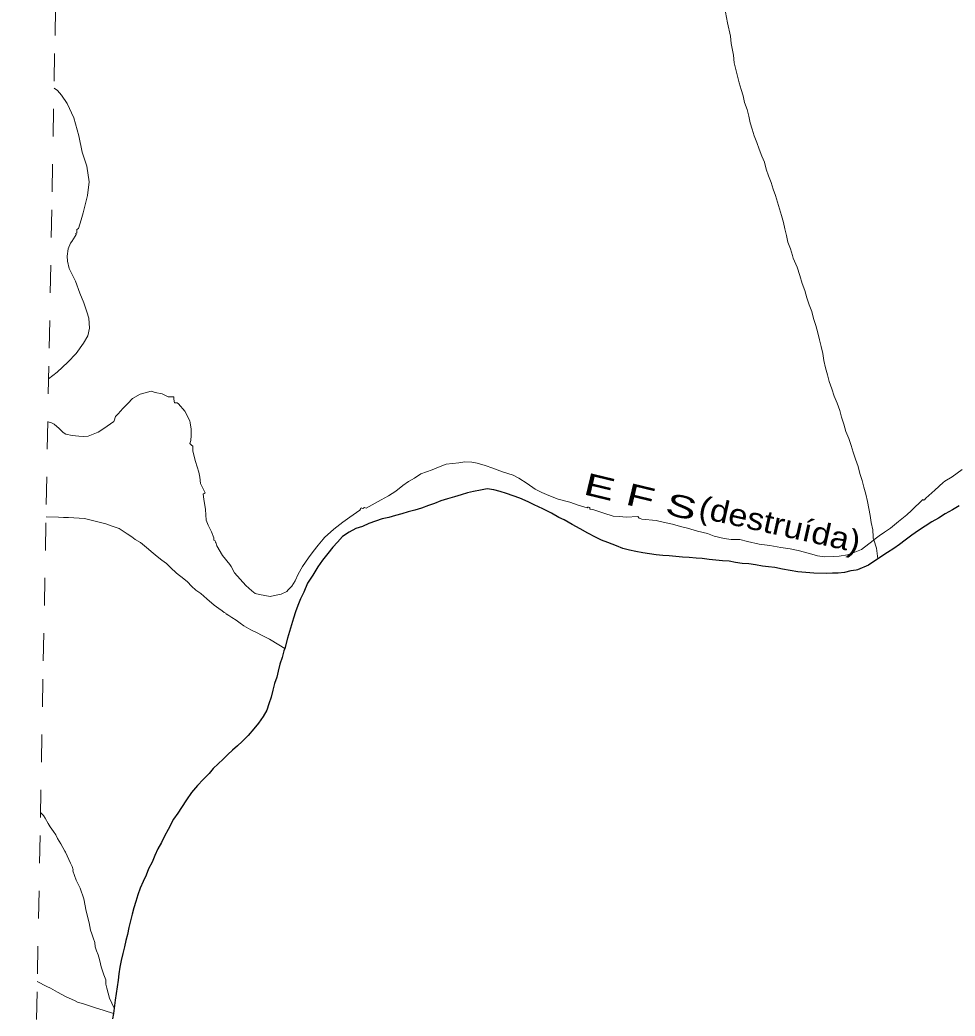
# Model space of a CAD drawing. Extents: x 781.9 to 808.1, y 7453.3 to 7481.5.
# Drawn here: x 782.028 to 785.41, y 7463.258 to 7466.859 of the extents above; entities that cross this region are included whole.
import ezdxf
from ezdxf.enums import TextEntityAlignment as Align

# ---------------------------------------------------------------- set-up
doc = ezdxf.new("R2010")
doc.units = 0
doc.header["$LTSCALE"] = 0.032
for name, pattern in [('DOTTED', [1.5, 0.3, -1.2]), ('LONG_DASHED', [7.5, 6, -1.5]), ('MEDIUM_DASHED', [4.5, 3, -1.5]), ('SHORT_DASHED', [2.7, 1.5, -1.2])]:
    doc.linetypes.add(name, pattern=pattern)
for name, color, linetype, lineweight in [('19', 7, 'DOTTED', 13), ('35', 7, 'SHORT_DASHED', 13), ('4', 7, 'LONG_DASHED', 25), ('5', 7, 'LONG_DASHED', 13), ('6', 7, 'MEDIUM_DASHED', 13)]:
    doc.layers.add(name, color=color, linetype=linetype, lineweight=lineweight)
doc.layers.add('61', color=7, linetype='Continuous')

msp = doc.modelspace()

# ---------------------------------------------------------------- linework, layer by layer
at = {"layer": '19'}
for points in [[(782.1515, 7466.6129), (782.1639, 7466.6037), (782.1791, 7466.5869), (782.1988, 7466.5576), (782.2233, 7466.5051), (782.2406, 7466.4397), (782.2538, 7466.3815), (782.2703, 7466.3306), (782.2791, 7466.2744), (782.2731, 7466.2243), (782.2591, 7466.1718), (782.2567, 7466.1613), (782.2502, 7466.137), (782.2397, 7466.1053), (782.234, 7466.1013), (782.234, 7466.094), (782.234, 7466.0891), (782.2307, 7466.0875), (782.2315, 7466.0834), (782.2275, 7466.0778), (782.2157, 7466.0583), (782.2105, 7466.0518), (782.2024, 7466.0316), (782.1996, 7466.0055), (782.2004, 7465.9871), (782.2068, 7465.9606), (782.2289, 7465.9145), (782.2449, 7465.872), (782.2597, 7465.8363), (782.2702, 7465.8034), (782.2778, 7465.7805), (782.2802, 7465.7444), (782.2734, 7465.7175), (782.2581, 7465.6903), (782.232, 7465.6538), (782.2015, 7465.6217), (782.1634, 7465.586), (782.1318, 7465.5621)], [(782.4351, 7465.4908), (782.4183, 7465.4732), (782.4007, 7465.4548), (782.3831, 7465.4356), (782.3743, 7465.4259), (782.3685, 7465.4105), (782.3678, 7465.4081)], [(783.9157, 7465.1505), (783.8917, 7465.1633), (783.8621, 7465.1841), (783.8325, 7465.2025), (783.8117, 7465.2137), (783.7733, 7465.2257), (783.7389, 7465.2385), (783.7109, 7465.2481), (783.6813, 7465.2569), (783.6621, 7465.2609), (783.6373, 7465.2617), (783.6149, 7465.2585), (783.5693, 7465.2529), (783.5357, 7465.2401), (783.519, 7465.233), (783.4777, 7465.2183), (783.4553, 7465.2032), (783.4329, 7465.1912), (783.4129, 7465.176), (783.3881, 7465.156), (783.3617, 7465.1384), (783.3345, 7465.1248), (783.2807, 7465.0943), (783.2742, 7465.0968), (783.2685, 7465.0935), (783.2628, 7465.0951), (783.2612, 7465.0927), (783.258, 7465.087), (783.2215, 7465.0619), (783.1964, 7465.0441), (783.1631, 7465.0181), (783.1298, 7464.9889), (783.125, 7464.9824), (783.1066, 7464.9608), (783.089, 7464.9376), (783.0722, 7464.9152), (783.0498, 7464.8832), (783.0346, 7464.8552), (783.0234, 7464.832), (783.0114, 7464.8128), (782.9986, 7464.7992), (782.9936, 7464.7935), (782.9734, 7464.7838), (782.9491, 7464.7789), (782.9337, 7464.7749), (782.894, 7464.7822), (782.8785, 7464.7862), (782.8664, 7464.7951), (782.8453, 7464.8146), (782.8039, 7464.8608), (782.7918, 7464.8835), (782.7869, 7464.8908), (782.7609, 7464.9233), (782.7399, 7464.9581), (782.7366, 7464.9702), (782.735, 7464.9711), (782.7342, 7464.9768), (782.7294, 7464.9792), (782.7294, 7464.9873), (782.7204, 7465.0084), (782.7091, 7465.0327), (782.7018, 7465.0514), (782.6994, 7465.0895), (782.6937, 7465.1268), (782.6913, 7465.1454), (782.6977, 7465.1494), (782.6815, 7465.1835), (782.6783, 7465.2062), (782.675, 7465.2249), (782.6637, 7465.263), (782.654, 7465.3003), (782.6532, 7465.3116), (782.6539, 7465.3181), (782.6483, 7465.3221), (782.6426, 7465.3278), (782.6467, 7465.3391), (782.6475, 7465.357), (782.6475, 7465.3797), (782.6434, 7465.4024), (782.6426, 7465.4097), (782.6248, 7465.4446), (782.6021, 7465.4713), (782.5972, 7465.4746), (782.5875, 7465.4754), (782.5842, 7465.4884), (782.5842, 7465.4916), (782.585, 7465.4972), (782.5648, 7465.4973), (782.5591, 7465.4997), (782.5421, 7465.507), (782.5178, 7465.5119), (782.5023, 7465.5167), (782.4626, 7465.5062), (782.4358, 7465.4908), (782.4351, 7465.4908)], [(782.3678, 7465.4081), (782.3321, 7465.3822), (782.3113, 7465.3686), (782.2929, 7465.3614), (782.2753, 7465.355), (782.2577, 7465.3534), (782.2409, 7465.3542), (782.2169, 7465.3566), (782.1945, 7465.3614), (782.1841, 7465.3678), (782.1697, 7465.3822), (782.1522, 7465.3982), (782.1418, 7465.403), (782.1289, 7465.4058)], [(785.4357, 7465.2338), (785.3992, 7465.207), (785.3733, 7465.1916), (785.3676, 7465.1876), (785.3368, 7465.16), (785.3043, 7465.13), (785.2995, 7465.1243), (785.2954, 7465.1227), (785.2938, 7465.1251), (785.2524, 7465.0854), (785.2362, 7465.0708), (785.2054, 7465.0465), (785.1762, 7465.0222), (785.1554, 7465.007), (785.1354, 7464.9942), (785.1162, 7464.9793)], [(784.0792, 7465.0959), (784.0679, 7465.0992), (784.0469, 7465.1049), (784.0165, 7465.1161), (783.9749, 7465.1273), (783.9405, 7465.1401), (783.9157, 7465.1505)], [(785.1162, 7464.9793), (785.1138, 7464.9774), (785.0722, 7464.9446), (785.0482, 7464.935), (785.021, 7464.9254), (784.9906, 7464.9214), (784.9706, 7464.9198), (784.9386, 7464.919), (784.9122, 7464.9222), (784.8842, 7464.9302), (784.8426, 7464.9414), (784.8138, 7464.9478), (784.7802, 7464.9526), (784.7402, 7464.9598), (784.7018, 7464.9638), (784.6594, 7464.9742), (784.6314, 7464.9806), (784.6002, 7464.9814), (784.5754, 7464.9846), (784.5394, 7464.9934), (784.5146, 7465.0022), (784.4782, 7465.0116), (784.443, 7465.022), (784.4166, 7465.0276), (784.3877, 7465.0364), (784.3542, 7465.0436), (784.3286, 7465.05), (784.2771, 7465.0546), (784.2714, 7465.057), (784.2682, 7465.0578), (784.2625, 7465.0643), (784.2204, 7465.0619), (784.196, 7465.0643), (784.1741, 7465.0652), (784.1393, 7465.0765), (784.1036, 7465.0878), (784.0922, 7465.0903), (784.089, 7465.0911), (784.0898, 7465.0968), (784.0841, 7465.0984), (784.0817, 7465.0984), (784.0792, 7465.0959)]]:
    msp.add_lwpolyline(points, dxfattribs=at)
at = {"layer": '35'}
msp.add_lwpolyline([(782.0281, 7460.0199), (782.0387, 7460.5852), (782.0493, 7461.1504), (782.0599, 7461.7157), (782.0704, 7462.2809), (782.081, 7462.8462), (782.0916, 7463.4115), (782.1022, 7463.9767), (782.1127, 7464.542), (782.1233, 7465.1072), (782.1339, 7465.6725), (782.1444, 7466.2377), (782.155, 7466.803), (782.1655, 7467.3682)], dxfattribs=at)
at = {"layer": '4'}
for points in [[(784.5447, 7464.9062), (784.5203, 7464.9087), (784.496, 7464.9119), (784.4733, 7464.9135), (784.449, 7464.916), (784.4247, 7464.9176), (784.4004, 7464.92), (784.376, 7464.9216), (784.3533, 7464.9232), (784.329, 7464.9257), (784.3047, 7464.9289), (784.2804, 7464.933), (784.256, 7464.9378), (784.2333, 7464.9427), (784.209, 7464.9484), (784.1855, 7464.9581), (784.1539, 7464.9703), (784.1312, 7464.9792), (784.1093, 7464.9897), (784.0817, 7465.0043), (784.0541, 7465.0197), (784.0257, 7465.0351), (783.9966, 7465.0522), (783.9771, 7465.0603), (783.9503, 7465.0765), (783.9196, 7465.0919), (783.888, 7465.1065), (783.8668, 7465.117), (783.8361, 7465.13), (783.8117, 7465.1389), (783.7874, 7465.1478), (783.7647, 7465.1551), (783.742, 7465.1608), (783.7177, 7465.1641), (783.6934, 7465.1592), (783.669, 7465.1551), (783.6463, 7465.1495), (783.6236, 7465.143), (783.5993, 7465.1357), (783.575, 7465.1276), (783.5507, 7465.1203), (783.528, 7465.1113), (783.5053, 7465.104), (783.4809, 7465.0943), (783.4566, 7465.087), (783.4323, 7465.0805), (783.4096, 7465.0741), (783.3869, 7465.0676), (783.3626, 7465.0611), (783.3383, 7465.0554), (783.3139, 7465.0473), (783.2896, 7465.0384), (783.2669, 7465.0286), (783.2426, 7465.0206), (783.2183, 7465.0075), (783.1947, 7464.9922), (783.1761, 7464.9719), (783.1599, 7464.9532), (783.1412, 7464.9306), (783.1226, 7464.9062), (783.1055, 7464.8827), (783.0869, 7464.8527), (783.0683, 7464.8235), (783.0545, 7464.7911), (783.0423, 7464.7668), (783.0334, 7464.7425), (783.0245, 7464.7198), (783.018, 7464.6971), (783.0107, 7464.6727), (783.0026, 7464.6484), (782.9953, 7464.6241), (782.986, 7464.5874)], [(785.4252, 7465.1024), (785.4008, 7465.0886), (785.3749, 7465.074), (785.3497, 7465.0586), (785.3261, 7465.0449), (785.3019, 7465.0294), (785.2776, 7465.0141), (785.2541, 7464.9962), (785.2298, 7464.9784), (785.2087, 7464.963), (785.1884, 7464.9484), (785.1657, 7464.9338), (785.1305, 7464.9114)], [(785.1305, 7464.9114), (785.0969, 7464.8882), (785.0577, 7464.8713), (785.053, 7464.8697), (785.0327, 7464.8673), (785.01, 7464.8616), (784.9873, 7464.86), (784.9663, 7464.86), (784.9452, 7464.8584), (784.8996, 7464.8592), (784.842, 7464.8648), (784.786, 7464.8736), (784.7587, 7464.8795), (784.736, 7464.8827), (784.7133, 7464.8852), (784.689, 7464.8892)], [(784.689, 7464.8892), (784.6647, 7464.8933), (784.6403, 7464.8949), (784.616, 7464.8981), (784.5933, 7464.9022), (784.569, 7464.9038), (784.5447, 7464.9062)], [(782.986, 7464.5874), (782.9831, 7464.5787), (782.9766, 7464.5544), (782.9677, 7464.53), (782.9621, 7464.5057), (782.9572, 7464.483), (782.9483, 7464.4603), (782.9434, 7464.436), (782.9369, 7464.4117), (782.9288, 7464.3874), (782.9207, 7464.3647), (782.9077, 7464.3419), (782.8915, 7464.3176), (782.8745, 7464.2973), (782.8542, 7464.273), (782.8315, 7464.2511), (782.8145, 7464.2348), (782.7974, 7464.2195), (782.7796, 7464.2041), (782.7626, 7464.1871), (782.7448, 7464.1708), (782.7269, 7464.153), (782.7123, 7464.1352), (782.6912, 7464.1141)], [(782.6912, 7464.1141), (782.6701, 7464.0914), (782.6491, 7464.0663), (782.6305, 7464.0403), (782.6126, 7464.0128), (782.5996, 7463.9925), (782.5834, 7463.9698)], [(782.5834, 7463.9698), (782.564, 7463.9333), (782.551, 7463.909), (782.5396, 7463.8863), (782.5274, 7463.8636), (782.5161, 7463.8393), (782.5064, 7463.815), (782.4934, 7463.7906), (782.4845, 7463.7679), (782.474, 7463.7452), (782.4634, 7463.7209), (782.4545, 7463.6966), (782.4472, 7463.6723), (782.4399, 7463.6496), (782.4341, 7463.6269), (782.4286, 7463.6025), (782.4221, 7463.5782), (782.4172, 7463.5539), (782.4107, 7463.5312), (782.4058, 7463.5085), (782.4002, 7463.4842), (782.3945, 7463.4598), (782.3896, 7463.4355), (782.3864, 7463.4112), (782.3832, 7463.3885), (782.3799, 7463.3642), (782.3759, 7463.3398), (782.3726, 7463.3155), (782.3686, 7463.2875), (782.367, 7463.2683), (782.3634, 7463.2487)]]:
    msp.add_lwpolyline(points, dxfattribs=at)
at = {"layer": '5'}
for points in [[(785.1162, 7464.9793), (785.1138, 7464.9865), (785.1138, 7464.9906), (785.1122, 7465.0165), (785.1073, 7465.0424), (785.1033, 7465.0684), (785.0984, 7465.0927), (785.0935, 7465.1187), (785.0879, 7465.1446), (785.0806, 7465.1706), (785.0741, 7465.1949), (785.066, 7465.2192), (785.0595, 7465.2451), (785.0498, 7465.2711), (785.0417, 7465.297), (785.0343, 7465.3214), (785.0263, 7465.3457), (785.0157, 7465.3716), (785.0084, 7465.3976), (784.9995, 7465.4235), (784.993, 7465.4478), (784.9841, 7465.4738), (784.9727, 7465.4997), (784.9646, 7465.5257), (784.9549, 7465.5516), (784.9484, 7465.5759), (784.9411, 7465.6019), (784.9355, 7465.6278), (784.9314, 7465.6538), (784.9257, 7465.6781), (784.92, 7465.7024), (784.9135, 7465.7284), (784.9063, 7465.7543), (784.8982, 7465.7802), (784.8917, 7465.8046), (784.8827, 7465.8289), (784.8746, 7465.8548), (784.8665, 7465.8808), (784.8576, 7465.9067), (784.8493, 7465.9351), (784.8396, 7465.9655), (784.8252, 7465.9983), (784.8228, 7466.0073), (784.8155, 7466.0316), (784.8057, 7466.0559), (784.8, 7466.0802), (784.7944, 7466.1045), (784.7895, 7466.1273), (784.7822, 7466.1516), (784.7757, 7466.1759), (784.7684, 7466.2002), (784.7603, 7466.2245), (784.7522, 7466.2472), (784.7449, 7466.2716), (784.7352, 7466.2959), (784.7271, 7466.3202), (784.7206, 7466.3445), (784.7117, 7466.3672), (784.702, 7466.3916), (784.693, 7466.4159), (784.6841, 7466.4402), (784.6768, 7466.4645), (784.6695, 7466.4872), (784.6638, 7466.5116), (784.6581, 7466.5359), (784.6492, 7466.5602), (784.6436, 7466.5845), (784.6363, 7466.6072), (784.629, 7466.6315), (784.6233, 7466.6559), (784.6176, 7466.6802), (784.6111, 7466.7045), (784.6085, 7466.7312), (784.6005, 7466.7736), (784.5974, 7466.8), (784.5876, 7466.8488), (784.5804, 7466.8872)], [(785.1305, 7464.9114), (785.1259, 7464.9497), (785.1162, 7464.9793)], [(782.0911, 7463.3834), (782.1258, 7463.3652), (782.1391, 7463.3593), (782.1643, 7463.3447), (782.1951, 7463.3285), (782.2259, 7463.3147), (782.2364, 7463.309), (782.2576, 7463.3033), (782.2977, 7463.2889), (782.3329, 7463.2785), (782.367, 7463.2683)]]:
    msp.add_lwpolyline(points, dxfattribs=at)
at = {"layer": '6'}
for points in [[(782.1225, 7465.0627), (782.1675, 7465.0619), (782.1853, 7465.0603), (782.2042, 7465.0609), (782.2616, 7465.0565), (782.3053, 7465.0465), (782.3199, 7465.0424), (782.3394, 7465.0375), (782.3621, 7465.0294), (782.3872, 7465.0205), (782.3977, 7465.0132), (782.4156, 7465.0019), (782.4326, 7464.9905), (782.4448, 7464.9816), (782.4642, 7464.9702), (782.4861, 7464.9516), (782.5105, 7464.9314), (782.525, 7464.92), (782.5413, 7464.9062), (782.5583, 7464.894), (782.5728, 7464.8795), (782.5939, 7464.8592), (782.6207, 7464.8389), (782.6337, 7464.8276), (782.6491, 7464.813), (782.6645, 7464.7984), (782.6823, 7464.7854), (782.7042, 7464.7668), (782.731, 7464.7433), (782.7472, 7464.7319), (782.7594, 7464.7238), (782.7667, 7464.7173), (782.7731, 7464.7149), (782.7739, 7464.7116), (782.7771, 7464.7116), (782.778, 7464.71), (782.7837, 7464.7068), (782.795, 7464.6995), (782.8096, 7464.6897), (782.8242, 7464.6792), (782.838, 7464.6695), (782.8631, 7464.6549), (782.8858, 7464.6435), (782.9021, 7464.6354), (782.9167, 7464.6281), (782.9313, 7464.6208), (782.9651, 7464.6002), (782.986, 7464.5874)], [(782.1025, 7463.9946), (782.1129, 7463.9837), (782.1194, 7463.9741), (782.1302, 7463.9544), (782.1375, 7463.9431), (782.1496, 7463.926), (782.1586, 7463.9139), (782.1643, 7463.9009), (782.1756, 7463.8814), (782.191, 7463.8547), (782.1926, 7463.8506), (782.1991, 7463.8377), (782.2048, 7463.8247), (782.2105, 7463.8117), (782.2169, 7463.7987), (782.2202, 7463.7866), (782.2195, 7463.7833), (782.2319, 7463.7492), (782.2456, 7463.7203), (782.2588, 7463.6822), (782.2677, 7463.6381), (782.2785, 7463.596), (782.2834, 7463.5693), (782.2883, 7463.5555), (782.2931, 7463.5409), (782.2988, 7463.5247), (782.3004, 7463.5085), (782.3053, 7463.4939), (782.311, 7463.4793), (782.3158, 7463.4631), (782.3199, 7463.4469), (782.3224, 7463.4363), (782.3321, 7463.408), (782.3385, 7463.3901), (782.3394, 7463.3739), (782.3426, 7463.3593), (782.3526, 7463.3228), (782.3686, 7463.2875)]]:
    msp.add_lwpolyline(points, dxfattribs=at)

# ---------------------------------------------------------------- texts
at = {"layer": '61'}
for s, rotation, width, p in [('E F S', 346.445, 1.55, (784.2633, 7465.0969)), ('(destruída)', 347.471, 1.15, (784.7679, 7464.9968))]:
    msp.add_text(s, height=0.08, rotation=rotation, dxfattribs=dict(at, width=width)).set_placement(p, align=Align.CENTER)

doc.saveas('drawing.dxf')
